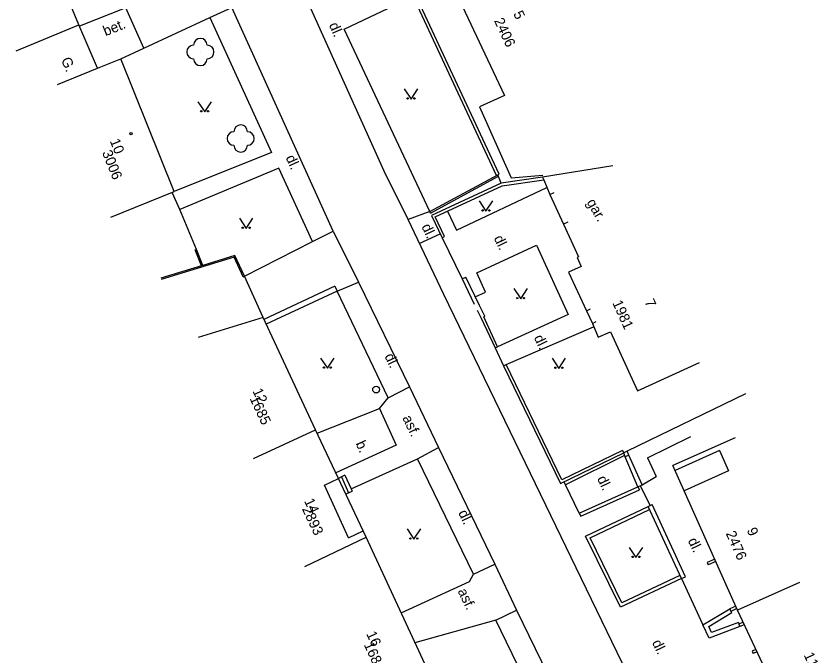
# Model space of a CAD drawing. Extents: x -584400 to -581602, y -1210894 to -1208793.
# Drawn here: x -583238.3 to -583179.4, y -1209702.4 to -1209655.4 of the extents above; entities that cross this region are included whole.
import ezdxf

# ---------------------------------------------------------------- set-up
doc = ezdxf.new("R2010")
doc.units = 0
for name, color, linetype in [('BUDOVY_MĚŘ', 7, 'Continuous'), ('POMOC_POPIS', 7, 'Continuous'), ('ROZHRANÍ_PLOCH', 7, 'Continuous'), ('ZELEŇ', 7, 'Continuous'), ('ZN_BUDOV', 7, 'Continuous'), ('ZN_DOPLŇKOVÉ', 7, 'Continuous'), ('ZN_KULTUR', 7, 'Continuous'), ('Č_POPIS_EVID', 7, 'Continuous')]:
    doc.layers.add(name, color=color, linetype=linetype)

msp = doc.modelspace()

# ---------------------------------------------------------------- linework, layer by layer
at = {"layer": 'BUDOVY_MĚŘ'}
for points in [[(-583211.55, -1209648.2), (-583209.41, -1209652.82), (-583208.19, -1209652.3), (-583207.46, -1209653.94), (-583206.14, -1209653.36), (-583202.42, -1209661.28), (-583204.26, -1209662.1), (-583201.93, -1209667.31), (-583199.6, -1209667.12)], [(-583233.65, -1209656.08), (-583234.95, -1209652.93)], [(-583238.27, -1209657.99), (-583233.65, -1209656.08)], [(-583232.29, -1209659.27), (-583233.65, -1209656.08)], [(-583232.29, -1209659.27), (-583230.59, -1209658.59)], [(-583231.3, -1209670.2), (-583226.66, -1209668.33), (-583230.59, -1209658.59)], [(-583235.23, -1209660.46), (-583232.29, -1209659.27)], [(-583194.47, -1209666.43), (-583199.62, -1209667.28), (-583199.54, -1209667.47), (-583199.08, -1209668.53)], [(-583199.08, -1209668.53), (-583198.76, -1209668.39)], [(-583199.08, -1209668.53), (-583198.09, -1209670.71)], [(-583197.77, -1209670.57), (-583198.09, -1209670.71)], [(-583198.09, -1209670.71), (-583196.98, -1209673.12), (-583197.09, -1209673.17), (-583196.8, -1209673.83), (-583197.71, -1209674.25), (-583196.4, -1209677.08)], [(-583196.4, -1209677.08), (-583196.11, -1209676.94)], [(-583196.4, -1209677.08), (-583195.97, -1209678.01)], [(-583216.29, -1209685.81), (-583220.13, -1209677.58), (-583224.91, -1209679.04)], [(-583195.97, -1209678.01), (-583195.68, -1209677.87)], [(-583195.97, -1209678.01), (-583195.55, -1209679.01), (-583194.63, -1209678.62), (-583192.66, -1209682.94), (-583188.11, -1209680.87)], [(-583220.83, -1209687.92), (-583216.29, -1209685.81)], [(-583212.56, -1209693.7), (-583216.29, -1209685.81)], [(-583185.48, -1209686.41), (-583190.05, -1209688.44)], [(-583185.32, -1209699.05), (-583190.05, -1209688.44)], [(-583217.08, -1209695.84), (-583212.56, -1209693.7)], [(-583207.21, -1209705.38), (-583207.17, -1209705.36), (-583212.56, -1209693.7)], [(-583180.76, -1209697.01), (-583185.32, -1209699.05)], [(-583180.91, -1209706.16), (-583181.8, -1209706.57), (-583185.32, -1209699.05)]]:
    msp.add_lwpolyline(points, dxfattribs=at)
at = {"layer": 'ROZHRANÍ_PLOCH'}
for points in [[(-583209.5, -1209670.38), (-583211.26, -1209666.83), (-583219.41, -1209648.67)], [(-583207.91, -1209669.8), (-583214.19, -1209656.41), (-583209.11, -1209653.99)], [(-583203, -1209667.14), (-583209.11, -1209653.99)], [(-583228.9, -1209657.8), (-583230.22, -1209654.84), (-583233.61, -1209656.18)], [(-583224.04, -1209655.55), (-583222.44, -1209654.82)], [(-583214.99, -1209671.23), (-583222.44, -1209654.82)], [(-583228.9, -1209657.8), (-583224.04, -1209655.55)], [(-583224.04, -1209655.55), (-583219.52, -1209665.46), (-583226.66, -1209668.33)], [(-583230.59, -1209658.59), (-583228.9, -1209657.8)], [(-583216.52, -1209671.99), (-583218.98, -1209666.6), (-583226.25, -1209669.65)], [(-583207.91, -1209669.8), (-583202.91, -1209667.09)], [(-583207.85, -1209669.9), (-583202.87, -1209667.2)], [(-583206.59, -1209669.76), (-583205.94, -1209671.16), (-583199.32, -1209668.03)], [(-583207.91, -1209669.8), (-583209.5, -1209670.38)], [(-583207.85, -1209669.9), (-583207.91, -1209669.8)], [(-583188.54, -1209713.73), (-583206.86, -1209675.87), (-583209.5, -1209670.38)], [(-583216.52, -1209671.99), (-583214.99, -1209671.23)], [(-583214.99, -1209671.23), (-583213.14, -1209674.98)], [(-583208.68, -1209672.13), (-583207.13, -1209671.43)], [(-583221.5, -1209674.54), (-583216.52, -1209671.99)], [(-583204.56, -1209676.06), (-583203.81, -1209675.7), (-583204.44, -1209674.3), (-583200.07, -1209672.27), (-583197.75, -1209677.36), (-583202.92, -1209679.72)], [(-583214.71, -1209675.64), (-583213.14, -1209674.98)], [(-583213.14, -1209674.98), (-583209.4, -1209682.66)], [(-583214.88, -1209675.27), (-583220.07, -1209677.71)], [(-583214.88, -1209675.27), (-583214.71, -1209675.64)], [(-583214.71, -1209675.64), (-583219.9, -1209678.07)], [(-583210.95, -1209683.46), (-583214.71, -1209675.64)], [(-583202.3, -1209681.02), (-583195.89, -1209678.25)], [(-583210.95, -1209683.46), (-583209.4, -1209682.66)], [(-583209.4, -1209682.66), (-583207.25, -1209687.1)], [(-583211.59, -1209684.24), (-583210.95, -1209683.46)], [(-583216.17, -1209686.06), (-583211.59, -1209684.24)], [(-583211.59, -1209684.24), (-583210.38, -1209686.95), (-583214.8, -1209688.96)], [(-583191.91, -1209687.87), (-583188.74, -1209686.3)], [(-583208.81, -1209687.95), (-583207.25, -1209687.1)], [(-583207.25, -1209687.1), (-583203.13, -1209695.67)], [(-583186.64, -1209687.34), (-583189.89, -1209688.79)], [(-583186.64, -1209687.34), (-583185.98, -1209688.83), (-583189.23, -1209690.28)], [(-583193.6, -1209687.71), (-583197.95, -1209689.85)], [(-583191.91, -1209687.87), (-583191.29, -1209689.25)], [(-583213.68, -1209690.14), (-583208.81, -1209687.95)], [(-583204.7, -1209696.4), (-583208.81, -1209687.95)], [(-583213.87, -1209693.73), (-583215.64, -1209689.87), (-583214.61, -1209689.38)], [(-583214.39, -1209689.27), (-583214.61, -1209689.38)], [(-583214.13, -1209689.14), (-583214.39, -1209689.27)], [(-583214.39, -1209689.27), (-583213.87, -1209690.43)], [(-583214.13, -1209689.14), (-583213.68, -1209690.14)], [(-583196.93, -1209691.93), (-583197.95, -1209689.85), (-583198.05, -1209689.64)], [(-583192.32, -1209689.86), (-583191.29, -1209689.25)], [(-583213.68, -1209690.14), (-583213.6, -1209690.31)], [(-583196.93, -1209691.93), (-583192.62, -1209689.99), (-583192.5, -1209690.21)], [(-583196.93, -1209691.93), (-583196.82, -1209692.15), (-583192.5, -1209690.21)], [(-583214.06, -1209690.52), (-583213.87, -1209690.43)], [(-583213.87, -1209690.43), (-583213.6, -1209690.31)], [(-583189.43, -1209696.73), (-583193.91, -1209698.83), (-583196.47, -1209693.62), (-583191.88, -1209691.43)], [(-583189.54, -1209696.5), (-583193.8, -1209698.5), (-583196.13, -1209693.74), (-583191.77, -1209691.66)], [(-583213.87, -1209693.73), (-583212.79, -1209693.22)], [(-583186.99, -1209695.3), (-583187.55, -1209695.55), (-583187.47, -1209695.73)], [(-583186.91, -1209695.48), (-583187.47, -1209695.73)], [(-583204.7, -1209696.4), (-583203.13, -1209695.67)], [(-583203.13, -1209695.67), (-583201.53, -1209699.05)], [(-583210.01, -1209699.24), (-583204.99, -1209696.94), (-583204.7, -1209696.4)], [(-583203.06, -1209699.78), (-583201.53, -1209699.05)], [(-583201.53, -1209699.05), (-583197.9, -1209706.54)], [(-583185.45, -1209698.76), (-583185.89, -1209698.96), (-583185.81, -1209699.14)], [(-583185.37, -1209698.94), (-583185.81, -1209699.14)], [(-583203.06, -1209699.78), (-583208.99, -1209701.45)], [(-583199.49, -1209707.15), (-583203.06, -1209699.78)], [(-583184.91, -1209699.94), (-583185.22, -1209700.08), (-583185.14, -1209700.26)], [(-583184.82, -1209700.12), (-583185.14, -1209700.26)], [(-583183.97, -1209701.93), (-583184.24, -1209702.06), (-583184.16, -1209702.24)], [(-583183.89, -1209702.11), (-583184.16, -1209702.24)]]:
    msp.add_lwpolyline(points, dxfattribs=at)
at = {"layer": 'ZELEŇ'}
for centre in [(-583224.74, -1209658.08), (-583221.78, -1209664.43)]:
    msp.add_circle(centre, 0.0005, dxfattribs=at)
for centre, start, end in [((-583224.74, -1209657.58), 0, 179.99999), ((-583225.24, -1209658.08), 89.99999, 269.99999), ((-583224.24, -1209658.08), 270, 89.99999), ((-583224.74, -1209658.58), 179.99999, 359.99999), ((-583221.78, -1209663.93), 0, 179.99999), ((-583222.28, -1209664.43), 89.99999, 269.99999), ((-583221.28, -1209664.43), 270, 89.99999), ((-583221.78, -1209664.93), 179.99999, 359.99999)]:
    msp.add_arc(centre, 0.5, start, end, dxfattribs=at)
at = {"layer": 'ZN_BUDOV'}
msp.add_circle((-583229.83, -1209664.08), 0.0875, dxfattribs=at)
at = {"layer": 'ZN_DOPLŇKOVÉ'}
for points in [[(-583202.82, -1209667.05), (-583208.93, -1209653.91)], [(-583202.91, -1209667.09), (-583202.82, -1209667.05)], [(-583202.67, -1209667.71), (-583202.91, -1209667.09)], [(-583199.62, -1209667.28), (-583202.66, -1209667.71)], [(-583202.66, -1209667.71), (-583207.77, -1209670.09), (-583206.99, -1209671.72), (-583206.81, -1209671.63)], [(-583206.81, -1209671.63), (-583207.5, -1209670.19), (-583202.6, -1209667.9), (-583199.54, -1209667.47)], [(-583202.67, -1209667.71), (-583202.66, -1209667.71)], [(-583226.25, -1209669.65), (-583226.81, -1209668.39)], [(-583225.03, -1209672.57), (-583226.25, -1209669.65)], [(-583206.99, -1209671.72), (-583205.52, -1209674.74)], [(-583224.66, -1209673.78), (-583225.13, -1209672.61), (-583225.03, -1209672.57)], [(-583224.57, -1209673.75), (-583225.03, -1209672.57)], [(-583221.59, -1209674.58), (-583222.27, -1209673.15), (-583227.61, -1209674.79)], [(-583221.59, -1209674.58), (-583221.5, -1209674.54), (-583222.22, -1209673.03), (-583224.57, -1209673.75)], [(-583224.66, -1209673.78), (-583227.63, -1209674.69)], [(-583224.57, -1209673.75), (-583224.66, -1209673.78)], [(-583220.13, -1209677.58), (-583221.5, -1209674.54)], [(-583205.52, -1209674.74), (-583205.25, -1209674.61)], [(-583205.52, -1209674.74), (-583204.64, -1209676.6)], [(-583202.92, -1209679.72), (-583203.94, -1209677.53), (-583203.85, -1209677.48), (-583204.26, -1209676.69), (-583205.25, -1209674.61)], [(-583204.42, -1209677.04), (-583204.12, -1209677.62), (-583203.1, -1209679.8), (-583202.92, -1209679.72)], [(-583203.1, -1209679.8), (-583202.48, -1209681.11)], [(-583202.48, -1209681.11), (-583202.3, -1209681.02)], [(-583202.48, -1209681.11), (-583198.3, -1209689.76), (-583193.67, -1209687.5)], [(-583193.76, -1209687.32), (-583198.21, -1209689.49), (-583202.3, -1209681.02)], [(-583184.72, -1209683.18), (-583193.41, -1209687.37)], [(-583193.76, -1209687.32), (-583193.67, -1209687.5)], [(-583193.41, -1209687.37), (-583193.67, -1209687.5)], [(-583193.57, -1209687.8), (-583193.67, -1209687.5)], [(-583193.28, -1209687.67), (-583193.57, -1209687.8)], [(-583192.62, -1209689.99), (-583193.57, -1209687.8)], [(-583193.28, -1209687.67), (-583193.41, -1209687.37)], [(-583192.32, -1209689.86), (-583193.28, -1209687.67)], [(-583192.62, -1209689.99), (-583192.32, -1209689.86)], [(-583192.47, -1209689.92), (-583191.73, -1209691.36)], [(-583189.43, -1209696.73), (-583191.88, -1209691.43), (-583191.59, -1209691.3)], [(-583189.43, -1209696.73), (-583189.14, -1209696.6), (-583191.59, -1209691.3)], [(-583189.43, -1209696.73), (-583187.85, -1209700.13)], [(-583185.14, -1209700.26), (-583187.39, -1209701.1), (-583187.85, -1209700.13), (-583185.89, -1209698.96)], [(-583185.25, -1209699.96), (-583187.22, -1209700.69), (-583187.43, -1209700.25), (-583185.72, -1209699.23)], [(-583185.81, -1209699.14), (-583185.72, -1209699.23)], [(-583185.25, -1209699.96), (-583185.22, -1209700.08)]]:
    msp.add_lwpolyline(points, dxfattribs=at)
for radius in [0.25, 0.0005]:
    msp.add_circle((-583211.84, -1209682.86), radius, dxfattribs=at)
at = {"layer": 'ZN_KULTUR'}
for points in [[(-583209.78, -1209660.79), (-583209.28, -1209661.54), (-583208.78, -1209660.79)], [(-583224.92, -1209661.73), (-583224.42, -1209662.48), (-583223.92, -1209661.73)], [(-583204.28, -1209669.01), (-583203.78, -1209669.76), (-583203.28, -1209669.01)], [(-583221.88, -1209670.28), (-583221.38, -1209671.03), (-583220.88, -1209670.28)], [(-583201.73, -1209675.45), (-583201.23, -1209676.2), (-583200.73, -1209675.45)], [(-583215.92, -1209680.55), (-583215.42, -1209681.3), (-583214.92, -1209680.55)], [(-583198.93, -1209680.56), (-583198.43, -1209681.31), (-583197.93, -1209680.56)], [(-583209.57, -1209693.09), (-583209.07, -1209693.84), (-583208.57, -1209693.09)], [(-583193.27, -1209694.44), (-583192.77, -1209695.19), (-583192.27, -1209694.44)]]:
    msp.add_lwpolyline(points, dxfattribs=at)
for centre in [(-583209.53, -1209661.49), (-583209.03, -1209661.49), (-583224.67, -1209662.43), (-583224.17, -1209662.43), (-583204.03, -1209669.71), (-583203.53, -1209669.71), (-583221.63, -1209670.98), (-583221.13, -1209670.98), (-583201.48, -1209676.15), (-583200.98, -1209676.15), (-583215.67, -1209681.25), (-583215.17, -1209681.25), (-583198.68, -1209681.26), (-583198.18, -1209681.26), (-583209.32, -1209693.79), (-583208.82, -1209693.79), (-583193.02, -1209695.14), (-583192.52, -1209695.14)]:
    msp.add_circle(centre, 0.05, dxfattribs=at)

# ---------------------------------------------------------------- texts
at = {"layer": 'POMOC_POPIS'}
for s, rotation, p in [('bet.', 21.93506, (-583231.7, -1209656.93)), ('dl.', 293.33972, (-583215.32, -1209656.09)), ('G.', 293.08814, (-583234.98, -1209658.65)), ('dl.', 294.51664, (-583218.5, -1209665.83)), ('gar.', 300.00001, (-583196.41, -1209669.11)), ('dl.', 295.26847, (-583208.53, -1209670.89)), ('dl.', 295.56727, (-583203.22, -1209671.74)), ('dl.', 295.56727, (-583200.28, -1209679.04)), ('dl.', 295.26847, (-583211.24, -1209680.4)), ('asf.', 295.56727, (-583209.93, -1209684.94)), ('b.', 294.08228, (-583213.36, -1209686.81)), ('dl.', 295.56727, (-583195.64, -1209689.39)), ('dl.', 295.26847, (-583205.83, -1209691.89)), ('dl.', 295.56727, (-583188.98, -1209693.94)), ('asf.', 295.56727, (-583205.87, -1209697.65)), ('dl.', 295.56727, (-583191.61, -1209701.42))]:
    msp.add_text(s, height=0.75, rotation=rotation, dxfattribs=at).set_placement(p)
at = {"layer": 'Č_POPIS_EVID'}
for s, rotation, p in [('2406', 295.02084, (-583203.2, -1209655.78)), ('5', 295.02084, (-583201.79, -1209655.26)), ('10', 291.97666, (-583231.4, -1209664.61)), ('3006', 291.97666, (-583231.97, -1209665.46)), ('7', 294.41001, (-583192.16, -1209676.41)), ('1981', 294.41001, (-583194.52, -1209676.49)), ('12', 294.96692, (-583220.93, -1209682.96)), ('1685', 294.96692, (-583221.14, -1209683.51)), ('14', 295.32588, (-583217.14, -1209691.04)), ('2893', 295.32588, (-583217.3, -1209691.62)), ('2476', 294.03014, (-583186.19, -1209693.42)), ('9', 294.03014, (-583184.65, -1209693.18)), ('16', 294.82403, (-583212.58, -1209700.79)), ('1686', 294.82403, (-583212.76, -1209701.58)), ('11', 295.08478, (-583180.47, -1209702.34))]:
    msp.add_text(s, height=0.75, rotation=rotation, dxfattribs=at).set_placement(p)

doc.saveas('drawing.dxf')
